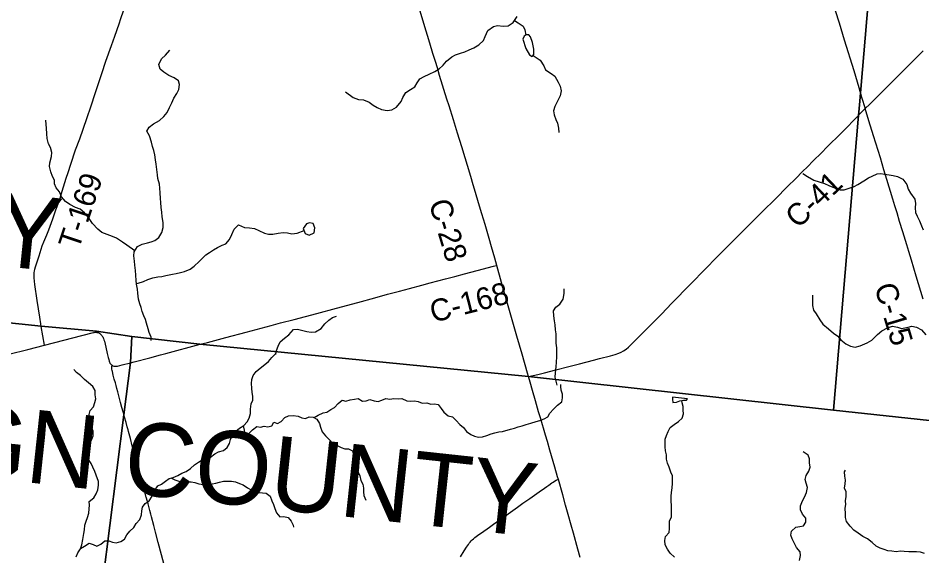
# Model space of a CAD drawing. Extents: x 0 to 1101, y 0 to 440.
# Drawn here: x 372 to 442.1, y 244.3 to 286 of the extents above; entities that cross this region are included whole.
import ezdxf

# ---------------------------------------------------------------- set-up
doc = ezdxf.new("R2010")
doc.units = 0
for name, color, linetype in [('GM_X_County_Road', 7, 'Continuous'), ('GM_X_County_Road_Text', 7, 'Continuous'), ('GM_X_County_Text', 7, 'Continuous'), ('GM_X_Minor_Lake', 7, 'Continuous'), ('GM_X_Minor_River', 7, 'Continuous'), ('GM_X_State_Route', 7, 'Continuous'), ('GM_X_Township', 7, 'Continuous'), ('GM_X_Township_Road', 7, 'Continuous'), ('GM_X_Township_Road_Text', 7, 'Continuous'), ('SH_Cut_Line', 7, 'Continuous')]:
    doc.layers.add(name, color=color, linetype=linetype)

msp = doc.modelspace()

# ---------------------------------------------------------------- linework, layer by layer
at = {"layer": 'GM_X_County_Road'}
msp.add_lwpolyline([(539, 244.322), (539, 402.783), (536.69, 402.914), (536.426, 402.929), (536.173, 402.942), (535.046, 402.998), (535.011, 403), (510.324, 404.394), (509.979, 404.414), (498.864, 405.041), (457.454, 407.541), (450.104, 407.972), (448.107, 408.104), (447.185, 397.096), (444.709, 367.542), (441.919, 334.219), (439.492, 305.784), (437.233, 279.3), (437.137, 278.176), (435.213, 255.629), (445.064, 254.562), (483.107, 250.705), (508.328, 247.799), (515.616, 246.993)], close=True, dxfattribs=at)
for points in [[(258.549, 348.4), (256.033, 323.55), (255.755, 319.941), (254.279, 304.355), (253.117, 292.401), (251.924, 280.12), (251.38, 274.519), (281.529, 271.532), (305.637, 269.297), (307.931, 269.05), (324.455, 267.133), (346.049, 265.027), (373.771, 262.138), (378.061, 261.761), (380.797, 261.323), (386.092, 260.749), (411.56, 258.243), (435.213, 255.629), (437.137, 278.176), (437.233, 279.3), (439.492, 305.784), (441.919, 334.219), (444.709, 367.542)], [(409.108, 266.85), (408.95, 267.398), (408.692, 268.293), (408.505, 268.937), (408.196, 270.012), (407.96, 270.836), (407.7, 271.693), (407.454, 272.513), (407.288, 273.085), (407.09, 273.745), (406.39, 276.043), (406.074, 277.095), (405.757, 278.129), (405.415, 279.214), (405.248, 279.747), (404.679, 281.579), (404.5, 282.168), (404.356, 282.649), (404.16, 283.29), (403.917, 284.072), (403.456, 285.606), (403.171, 286.551)], [(436.917, 278.231), (436.936, 278.251), (437.421, 278.747), (437.677, 279.002)], [(442.167, 264.219), (441.627, 266.023), (441.264, 267.256), (441.057, 267.934), (440.896, 268.449), (440.594, 269.448), (440.348, 270.25), (440.144, 270.928), (439.982, 271.463), (439.823, 271.98), (439.358, 273.513), (439.133, 274.263), (438.852, 275.191), (438.331, 276.883), (437.97, 278.058), (437.677, 279.002)], [(411.567, 258.227), (412.302, 258.395), (412.808, 258.518), (413.692, 258.75), (414.684, 259.008), (415.533, 259.224), (416.615, 259.502), (417.067, 259.616), (417.916, 259.83), (418.29, 259.94), (418.569, 260.041), (418.754, 260.122), (418.931, 260.221), (419.129, 260.356), (419.329, 260.519), (419.613, 260.786), (420.65, 261.831), (421.868, 263.064), (422.683, 263.909), (423.198, 264.448), (423.612, 264.879), (424.204, 265.473), (426.234, 267.529), (427.387, 268.696), (427.927, 269.237), (428.61, 269.924), (429.678, 270.992), (430.736, 272.043), (431.635, 272.937), (432.32, 273.621), (432.795, 274.095), (433.232, 274.528), (433.628, 274.921), (434.31, 275.609), (434.706, 276.004), (435.811, 277.114), (436.273, 277.574), (436.781, 278.093), (436.917, 278.231)], [(386.099, 260.733), (386.673, 260.878), (387.25, 261.028), (388.096, 261.254), (389.681, 261.676), (390.455, 261.882), (391.623, 262.2), (392.344, 262.388), (393.403, 262.654), (395.157, 263.116), (396.683, 263.536), (398.327, 263.981), (399.653, 264.344), (400.642, 264.605), (401.568, 264.85), (402.335, 265.054), (403.306, 265.32), (403.936, 265.487), (405.144, 265.808), (405.847, 265.992), (406.604, 266.193), (407.578, 266.445), (408.863, 266.785), (408.945, 266.807), (409.108, 266.85)], [(411.567, 258.227), (411.485, 258.493), (411.064, 259.956), (410.664, 261.357), (409.941, 263.883), (409.616, 265.05), (409.193, 266.557), (409.108, 266.85)], [(374.049, 260.664), (377.733, 261.619), (377.824, 261.641), (377.894, 261.657), (377.968, 261.66), (378.025, 261.66), (378.086, 261.654), (378.147, 261.646), (378.192, 261.633), (378.241, 261.615), (378.278, 261.593), (378.324, 261.567), (378.375, 261.525), (378.428, 261.476), (378.476, 261.423), (378.514, 261.368), (378.558, 261.303), (378.591, 261.236), (378.619, 261.172), (378.649, 261.087), (378.688, 260.961), (378.793, 260.5), (378.899, 260.027), (378.974, 259.712), (379.017, 259.548), (379.043, 259.421), (379.066, 259.357), (379.092, 259.303), (379.115, 259.263), (379.17, 259.194), (379.225, 259.14), (379.276, 259.101)], [(380.703, 259.3), (380.994, 259.377), (382.218, 259.691), (383.028, 259.905), (383.441, 260.016), (386.099, 260.733)], [(348.992, 254.096), (350.05, 254.366), (351.365, 254.717), (352.592, 255.034), (353.512, 255.274), (354.755, 255.597), (355.295, 255.734), (357.96, 256.413), (360.999, 257.229), (362.306, 257.594), (363.84, 258.009), (365.403, 258.438), (366.73, 258.783), (369.053, 259.375), (371.278, 259.954), (372.737, 260.332), (374.049, 260.664)], [(379.276, 259.101), (379.306, 259.082), (379.346, 259.061), (379.403, 259.041), (379.454, 259.032), (379.505, 259.027), (379.563, 259.026), (379.629, 259.032), (379.7, 259.041), (380.057, 259.13), (380.703, 259.3)], [(413.882, 250.257), (413.829, 250.453), (413.617, 251.206), (413.357, 252.081), (413.232, 252.509), (413.033, 253.187), (412.887, 253.688), (412.493, 255.029), (412.355, 255.493), (412.104, 256.352), (411.874, 257.158), (411.686, 257.803), (411.567, 258.227)], [(415.582, 244.21), (415.4, 244.855), (415.052, 246.073), (414.875, 246.701), (414.645, 247.527), (414.44, 248.263), (414.221, 249.049), (413.882, 250.257)]]:
    msp.add_lwpolyline(points, dxfattribs=at)
at = {"layer": 'GM_X_Minor_Lake'}
msp.add_line((423.902, 256.506), (422.728, 256.636), dxfattribs=at)
for points in [[(411.71, 284.568), (411.587, 284.719), (411.393, 284.723), (411.22, 284.623), (411.136, 284.384), (411.362, 283.66), (411.649, 283.175), (411.863, 283.034), (411.992, 283.203), (411.988, 283.603), (411.885, 284.142)], [(411.885, 284.142), (411.71, 284.568)], [(394.251, 269.329), (394.568, 269.186), (394.948, 269.362), (394.99, 269.75), (394.871, 270.095), (394.598, 270.157), (394.345, 270.07), (394.099, 269.72)], [(394.099, 269.72), (394.251, 269.329)], [(422.728, 256.636), (422.732, 256.479), (422.763, 256.205), (423.048, 256.247), (423.3, 256.346), (423.574, 256.4), (423.813, 256.408), (423.902, 256.506)]]:
    msp.add_lwpolyline(points, dxfattribs=at)
at = {"layer": 'GM_X_Minor_River'}
for points in [[(397.383, 280.315), (397.968, 279.87), (398.376, 279.714), (398.775, 279.684), (399.206, 279.516), (399.521, 279.27), (399.826, 279.104), (400.165, 278.938), (400.62, 278.861), (400.964, 278.912), (401.344, 279.122), (401.695, 279.562), (401.815, 279.88), (402.062, 280.252), (402.42, 280.486), (402.744, 280.697), (402.933, 281.014), (403.144, 281.307), (403.49, 281.495), (403.87, 281.671), (404.296, 281.88), (404.62, 282.069), (404.945, 282.383), (405.214, 282.687), (405.619, 283.022), (405.919, 283.188), (406.287, 283.307), (406.631, 283.404), (406.977, 283.558), (407.334, 283.723), (407.726, 283.955), (408.075, 284.292), (408.195, 284.61), (408.409, 285.063), (408.86, 285.364), (409.158, 285.438), (409.603, 285.407), (409.991, 285.412), (410.373, 285.679), (410.69, 286.142)], [(410.484, 285.84), (410.761, 285.66), (411.155, 285.402), (411.287, 285.113), (411.357, 284.702)], [(382.304, 261.02), (382.306, 261.271), (382.142, 261.64), (382.067, 261.927), (381.95, 262.364), (381.865, 262.662), (381.745, 262.95), (381.614, 263.261), (381.528, 263.572), (381.419, 263.859), (381.335, 264.238), (381.264, 264.697), (381.236, 264.995), (381.175, 265.384), (381.146, 265.671), (381.119, 266.083), (381.081, 266.449), (381.043, 266.862), (381.004, 267.182), (380.966, 267.595), (380.983, 267.903), (381.254, 268.321), (381.611, 268.486), (382.024, 268.604), (382.311, 268.679), (382.598, 268.788), (382.899, 269), (383.146, 269.407), (383.245, 269.782), (383.229, 270.171), (383.169, 270.607), (383.131, 270.973), (383.081, 271.34), (383.054, 271.729), (383.025, 272.027), (382.999, 272.473), (382.972, 272.828), (382.944, 273.16), (382.838, 273.585), (382.809, 273.872), (382.76, 274.273), (382.688, 274.697), (382.638, 275.041), (382.588, 275.419), (382.514, 275.763), (382.418, 276.074), (382.344, 276.395), (382.171, 276.89), (381.984, 277.259), (382.161, 277.576), (382.485, 277.822), (382.958, 278.076), (383.295, 278.39), (383.541, 278.706), (383.742, 279.091), (383.909, 279.454), (384.064, 279.805), (384.288, 280.167), (384.465, 280.495), (384.518, 280.883), (384.421, 281.17), (384.094, 281.394), (383.675, 281.561), (383.292, 281.831), (383, 282.054), (382.904, 282.433), (383.118, 282.875), (383.409, 283.144), (383.758, 283.526)], [(411.932, 283.123), (412.463, 282.76), (412.752, 282.32), (412.883, 282.02), (413.323, 281.738), (413.615, 281.515), (413.88, 281.053), (414.012, 280.753), (414.096, 280.386), (414.031, 279.998), (413.759, 279.489), (413.616, 279.171), (413.507, 278.842), (413.57, 278.532), (413.7, 278.164), (413.808, 277.865), (413.903, 277.485), (413.909, 277.154)], [(381.032, 267.978), (380.422, 268.428), (380.084, 268.64), (379.622, 268.957), (379.316, 269.088), (378.885, 269.233), (378.489, 269.412), (378.163, 269.67), (377.772, 270.1), (377.438, 270.552), (377.137, 270.934), (376.8, 271.215), (376.449, 271.347), (376.008, 271.572), (375.658, 271.796), (375.346, 272.168), (375.193, 272.548), (374.936, 272.85), (374.805, 273.161), (374.8, 273.458), (374.645, 273.747), (374.538, 274.103), (374.432, 274.505), (374.46, 274.802), (374.584, 275.303), (374.612, 275.599), (374.505, 275.978), (374.351, 276.267), (374.256, 276.692), (374.229, 277.047), (374.203, 277.482), (374.174, 277.768), (374.135, 278.112)], [(432.853, 273.971), (433.191, 273.736), (433.688, 273.464), (434.108, 273.33), (434.516, 273.186), (434.845, 273.054), (435.286, 272.852), (435.74, 272.695), (436.037, 272.712), (436.427, 272.842), (436.818, 272.961), (437.117, 273.115), (437.568, 273.404), (437.926, 273.638), (438.214, 273.77), (438.594, 273.945), (438.88, 273.963), (439.176, 273.923), (439.529, 273.86), (439.847, 273.82), (440.189, 273.745), (440.584, 273.532), (440.896, 273.114), (441.015, 272.769), (441.18, 272.458), (441.536, 271.982), (441.586, 271.638), (441.546, 271.319), (441.573, 270.953), (441.693, 270.665), (441.881, 270.307), (442.033, 269.904), (442.164, 269.604)], [(381.167, 265.456), (381.313, 265.462), (381.704, 265.603), (382.049, 265.746), (382.44, 265.887), (382.818, 265.96), (383.138, 266), (383.448, 266.063), (383.952, 266.157), (384.25, 266.231), (384.582, 266.294), (384.892, 266.368), (385.329, 266.566), (385.642, 266.8), (386.037, 267.159), (386.537, 267.664), (386.826, 267.853), (387.138, 268.053), (387.45, 268.242), (387.807, 268.407), (388.106, 268.527), (388.375, 268.865), (388.565, 269.25), (388.744, 269.659), (389.082, 269.995), (389.534, 269.793), (389.945, 269.762), (390.32, 269.71), (390.649, 269.555), (391.101, 269.352), (391.397, 269.278), (391.739, 269.272), (392.163, 269.344), (392.552, 269.394), (392.871, 269.366), (393.224, 269.302), (393.624, 269.352), (394.167, 269.544)], [(413.786, 257.555), (413.723, 257.882), (413.637, 258.169), (413.667, 258.512), (413.71, 258.98), (413.74, 259.356), (413.77, 259.767), (413.777, 260.11), (413.772, 260.453), (413.722, 260.809), (413.718, 261.186), (413.724, 261.529), (413.673, 261.861), (413.635, 262.228), (413.584, 262.56), (413.534, 262.927), (413.507, 263.328), (413.684, 263.622), (413.985, 263.845), (414.255, 264.24), (414.332, 264.662), (414.327, 265.027)], [(433.586, 264.548), (433.59, 264.125), (433.594, 263.748), (433.655, 263.381), (433.866, 263.08), (434.155, 262.629), (434.4, 262.304), (434.838, 261.93), (435.231, 261.603), (435.546, 261.357), (435.78, 261.067), (436.185, 260.762), (436.536, 260.596), (436.899, 260.52), (437.289, 260.616), (437.83, 260.846), (438.188, 261.057), (438.642, 261.494), (438.978, 261.763), (439.405, 262.006), (439.784, 262.125), (440.193, 262.049), (440.488, 261.952), (441.004, 262.057), (441.291, 262.143), (441.643, 262.068), (442.039, 261.844), (442.385, 261.471)], [(391.964, 259.927), (392.023, 260.247), (392.166, 260.575), (392.321, 260.916), (392.647, 261.207), (392.971, 261.464), (393.344, 261.88), (393.664, 261.908), (394.062, 261.798), (394.369, 261.724), (394.71, 261.672), (395.053, 261.7), (395.48, 261.967), (395.772, 262.316), (396.075, 262.607), (396.364, 262.808), (396.674, 262.905)], [(376.836, 244.907), (377.149, 245.084), (377.493, 245.298), (377.801, 245.215), (378.085, 245.076), (378.395, 245.244), (378.717, 245.493), (379.014, 245.502), (379.299, 245.385), (379.606, 245.336), (379.95, 245.447), (380.237, 245.628), (380.411, 245.946), (380.654, 246.241), (380.953, 246.524), (381.15, 246.843), (381.439, 247.149), (381.568, 247.502), (381.593, 247.811), (381.63, 248.097), (381.85, 248.392), (382.148, 248.584), (382.38, 248.947), (382.543, 249.335), (382.833, 249.767), (383.119, 249.89), (383.418, 250.116), (383.706, 250.33), (384.003, 250.408), (384.37, 250.553), (384.692, 250.744), (385.035, 250.856), (385.346, 251.093), (385.668, 251.376), (385.979, 251.602), (386.266, 251.782), (386.587, 251.882), (386.919, 251.982), (387.252, 252.242), (387.539, 252.399), (387.906, 252.499), (388.193, 252.736), (388.379, 253.032), (388.461, 253.34), (388.59, 253.625), (388.855, 253.965), (389.155, 254.226), (389.488, 254.429), (389.753, 254.723), (389.904, 255.008), (389.999, 255.373), (390.001, 255.693), (390.074, 256.116), (390.19, 256.401), (390.182, 256.71), (390.15, 256.996), (390.107, 257.339), (390.076, 257.694), (390.102, 257.991), (390.207, 258.311), (390.45, 258.629), (390.772, 258.877), (391.117, 259.16), (391.416, 259.397), (391.659, 259.704), (391.947, 259.999), (392.005, 260.101)], [(376.501, 244.244), (376.63, 244.563), (376.827, 244.881), (376.944, 245.189), (377.004, 245.589), (377.089, 246.057), (377.137, 246.342), (377.163, 246.697), (377.268, 247.016), (377.362, 247.301), (377.468, 247.632), (377.505, 247.963), (377.531, 248.26), (377.51, 248.546), (377.856, 248.829), (378.052, 249.125), (378.17, 249.444), (378.218, 249.798), (378.221, 250.084), (378.054, 250.589), (377.931, 250.876), (377.785, 251.197), (377.651, 251.484), (377.459, 251.795), (377.325, 252.082), (377.225, 252.369), (377.193, 252.655), (377.367, 252.962), (377.655, 253.246), (377.807, 253.633), (377.822, 253.988), (377.688, 254.332), (377.599, 254.642), (377.499, 254.997), (377.513, 255.294), (377.584, 255.591), (377.827, 255.886), (377.944, 256.205), (378.015, 256.502), (377.972, 256.8), (377.975, 257.154), (377.784, 257.465), (377.444, 257.754), (377.149, 257.997), (376.821, 258.32), (376.526, 258.54), (376.299, 258.783)], [(394.941, 255.041), (395.252, 255.244), (395.642, 255.412), (395.928, 255.478), (396.238, 255.681), (396.525, 255.839), (396.813, 256.145), (397.124, 256.394), (397.409, 256.322), (397.741, 256.411), (398.073, 256.476), (398.359, 256.531), (398.688, 256.322), (398.985, 256.353), (399.272, 256.442), (399.613, 256.336), (399.899, 256.288), (400.196, 256.399), (400.506, 256.534), (400.814, 256.474), (401.134, 256.528), (401.465, 256.49), (401.751, 256.534), (402.126, 256.336), (402.435, 256.333), (402.72, 256.341), (403.017, 256.282), (403.313, 256.176), (403.679, 256.195), (403.986, 256.09), (404.283, 256.11), (404.568, 256.061), (404.794, 255.762), (405.008, 255.462), (405.337, 255.185), (405.679, 255.102), (405.951, 254.813), (406.245, 254.502), (406.54, 254.282), (406.754, 253.959), (407.095, 253.727), (407.391, 253.61), (407.698, 253.539), (407.996, 253.559), (408.339, 253.647), (408.671, 253.781), (408.958, 253.859), (409.255, 253.947), (409.564, 253.979), (410.182, 254.156), (410.48, 254.222), (410.767, 254.334), (411.087, 254.399), (411.385, 254.5), (411.752, 254.622), (412.152, 254.756), (412.45, 254.81), (412.782, 254.956), (413.069, 255.102), (413.22, 255.398), (413.509, 255.704), (413.809, 256.021), (414.142, 256.281), (414.213, 256.578), (414.193, 256.864), (414.104, 257.162), (414.084, 257.448), (414.085, 257.609)], [(422.887, 244.213), (422.547, 244.537), (422.356, 244.836), (422.165, 245.181), (422.145, 245.524), (422.193, 245.832), (422.482, 246.127), (422.507, 246.436), (422.498, 246.744), (422.501, 247.042), (422.652, 247.338), (422.655, 247.635), (422.66, 248.253), (422.629, 248.539), (422.621, 248.951), (422.669, 249.248), (422.706, 249.591), (422.732, 249.945), (422.735, 250.231), (422.726, 250.528), (422.615, 250.827), (422.469, 251.194), (422.335, 251.516), (422.269, 251.825), (422.272, 252.168), (422.184, 252.478), (422.164, 252.787), (422.169, 253.37), (422.263, 253.667), (422.391, 253.963), (422.554, 254.27), (422.864, 254.507), (423.198, 254.733), (423.485, 254.994), (423.591, 255.336), (423.56, 255.622), (423.551, 255.908), (423.485, 256.195), (423.464, 256.378)], [(389.435, 254.396), (389.507, 254.062), (389.561, 253.742), (389.871, 253.819), (390.159, 254.091), (390.504, 254.35), (390.789, 254.314), (391.075, 254.391), (391.36, 254.331), (391.658, 254.397), (391.809, 254.693), (392.093, 254.599), (392.392, 254.733), (392.669, 255.062), (392.967, 255.174), (393.321, 255.216), (393.698, 255.167), (393.982, 255.039), (394.267, 254.979), (394.554, 255.102), (394.862, 255.088), (395.157, 254.913), (395.349, 254.58), (395.437, 254.293), (395.571, 253.937), (395.82, 253.626), (396.114, 253.338), (396.442, 252.991), (396.727, 252.886), (397.034, 252.734), (397.33, 252.629), (397.616, 252.614), (397.911, 252.463), (397.989, 252.176), (397.963, 251.868), (398.006, 251.524), (398.14, 251.18), (398.343, 250.869), (398.5, 250.536), (398.565, 250.181), (398.711, 249.882), (398.777, 249.573), (398.774, 249.287), (398.806, 249), (398.951, 248.633)], [(432.582, 243.963), (432.654, 244.363), (432.646, 244.649), (432.352, 244.972), (432.183, 245.271), (432.015, 245.638), (431.903, 245.937), (431.974, 246.233), (432.285, 246.539), (432.606, 246.605), (432.892, 246.648), (433.066, 246.932), (433.069, 247.253), (432.82, 247.552), (432.663, 247.885), (432.654, 248.206), (432.806, 248.582), (432.957, 248.878), (433.132, 249.242), (433.192, 249.619), (433.104, 249.952), (433.027, 250.25), (433.087, 250.569), (433.318, 250.888), (433.401, 251.196), (433.358, 251.539), (433.361, 251.837), (433.26, 252.123), (432.931, 252.344), (432.863, 252.39)], [(442.262, 244.514), (441.954, 244.62), (441.646, 244.645), (441.361, 244.648), (441.052, 244.639), (440.699, 244.665), (440.402, 244.68), (440.07, 244.648), (439.751, 244.686), (439.443, 244.723), (439.146, 244.817), (438.827, 244.912), (438.521, 245.086), (438.215, 245.352), (437.863, 245.641), (437.499, 245.827), (437.125, 246.094), (436.807, 246.326), (436.512, 246.626), (436.23, 246.983), (436.141, 247.293), (436.144, 247.59), (436.125, 248.025), (436.162, 248.31), (436.153, 248.597), (436.202, 248.916), (436.193, 249.282), (436.059, 249.581), (436.13, 249.901), (436.156, 250.186), (436.102, 250.507), (436.082, 250.839), (436.14, 250.964)], [(383.83, 250.363), (384.139, 250.223), (384.458, 250.129), (384.743, 250.081), (385.097, 250.066), (385.405, 250.074), (385.69, 250.015), (385.998, 249.92), (386.34, 249.871), (386.717, 249.879), (387.037, 249.911), (387.323, 249.965), (387.61, 250.042), (387.93, 250.108), (388.227, 250.128), (388.535, 250.114), (388.844, 250.077), (389.162, 249.948), (389.447, 249.842), (389.776, 249.588), (390.072, 249.436), (390.356, 249.331), (390.641, 249.237), (390.949, 249.222), (391.234, 249.185), (391.529, 248.954), (391.663, 248.598), (391.786, 248.311), (391.909, 247.99), (392.02, 247.668), (392.292, 247.357), (392.6, 247.377), (392.92, 247.305), (393.168, 247.017), (393.314, 246.707), (393.347, 246.558)]]:
    msp.add_lwpolyline(points, dxfattribs=at)
at = {"layer": 'GM_X_State_Route'}
for points in [[(435.072, 287.513), (435.645, 285.66), (436.041, 284.341), (436.782, 281.954), (437.175, 280.646)], [(437.175, 280.646), (437.399, 279.901), (437.677, 279.002), (438.036, 279.347), (439.548, 280.866), (441.444, 282.766), (442.162, 283.484)]]:
    msp.add_lwpolyline(points, dxfattribs=at)
at = {"layer": 'GM_X_Township'}
for points in [[(189.224, 280.089), (205.419, 278.858), (219.953, 277.58), (235.998, 275.889), (239.628, 275.54), (251.141, 274.543), (251.38, 274.519), (281.529, 271.532), (305.637, 269.297), (307.931, 269.05), (324.455, 267.133), (346.049, 265.027), (373.771, 262.138), (378.061, 261.761), (380.797, 261.323), (380.697, 259.316), (380.197, 255.256), (378.028, 238.099), (373.82, 204.757), (373.469, 201.961), (371.877, 189.376), (367.226, 152.429)], [(456.87, 41.812), (429.195, 44.697), (407.625, 46.582), (393.244, 47.835), (358.093, 49.313), (354.24, 49.634), (354.518, 51.702), (355.546, 60.287), (359.256, 91.672), (367.226, 152.429), (371.877, 189.376), (373.469, 201.961), (373.82, 204.757), (378.028, 238.099), (380.197, 255.256), (380.697, 259.316), (380.797, 261.323), (386.092, 260.749), (411.56, 258.243), (435.213, 255.629), (445.064, 254.562)]]:
    msp.add_lwpolyline(points, dxfattribs=at)
at = {"layer": 'GM_X_Township_Road'}
msp.add_line((374.049, 260.664), (373.778, 262.122), dxfattribs=at)
for points in [[(373.778, 262.122), (373.75, 262.323), (373.67, 262.844), (373.475, 264.12), (373.294, 265.357), (373.257, 265.629), (373.242, 265.882), (373.232, 266.044), (373.232, 266.17), (373.246, 266.309), (373.257, 266.397), (373.291, 266.567), (373.336, 266.732), (373.615, 267.599), (373.869, 268.358), (373.991, 268.67), (374.227, 269.217), (374.379, 269.616), (374.59, 270.187), (374.687, 270.471), (374.919, 271.156), (375.188, 271.885), (375.408, 272.595), (375.718, 273.614), (375.86, 274.057), (376.077, 274.694), (376.454, 275.797), (376.773, 276.658), (377.319, 278.244), (377.647, 279.231), (377.968, 280.188), (378.483, 281.724), (378.806, 282.675), (379.233, 283.888), (379.488, 284.611), (379.816, 285.586), (379.953, 285.987), (380.155, 286.595)], [(380.204, 255.24), (380.13, 255.503), (380.039, 255.842), (379.934, 256.211), (379.848, 256.524), (379.717, 257.034), (379.652, 257.301), (379.59, 257.535), (379.536, 257.732), (379.448, 258.037), (379.37, 258.325), (379.299, 258.609), (379.282, 258.699), (379.268, 258.813), (379.263, 258.893), (379.265, 258.976), (379.276, 259.101)], [(380.52, 254.087), (380.452, 254.328), (380.361, 254.667), (380.252, 255.067), (380.204, 255.24)], [(382.065, 248.357), (382.02, 248.53), (381.925, 248.886), (381.715, 249.678), (381.49, 250.482), (381.381, 250.874), (381.261, 251.323), (381.075, 252.026), (380.906, 252.636), (380.842, 252.869), (380.696, 253.434), (380.553, 253.966), (380.52, 254.087)], [(406.288, 244.261), (406.575, 244.721), (406.761, 245), (406.905, 245.206), (406.975, 245.304), (407.051, 245.398), (407.134, 245.491), (407.203, 245.561), (407.305, 245.655), (407.406, 245.744), (407.501, 245.82), (407.609, 245.903), (407.791, 246.035), (407.911, 246.122), (408.541, 246.558), (408.862, 246.781), (409.71, 247.389), (410.181, 247.724), (410.712, 248.104), (411.119, 248.399), (411.669, 248.784), (412.023, 249.024), (412.406, 249.291), (412.802, 249.569), (412.985, 249.698), (413.152, 249.816), (413.382, 249.975), (413.49, 250.048), (413.589, 250.111), (413.707, 250.182), (413.767, 250.215), (413.83, 250.242), (413.882, 250.257)], [(383.295, 243.723), (382.864, 245.364), (382.652, 246.156), (382.513, 246.678), (382.336, 247.343), (382.279, 247.556), (382.199, 247.835), (382.065, 248.357)]]:
    msp.add_lwpolyline(points, dxfattribs=at)
at = {"layer": 'SH_Cut_Line'}
for points in [[(445.064, 254.562), (435.213, 255.629), (411.56, 258.243), (386.092, 260.749), (380.797, 261.323), (378.061, 261.761), (373.771, 262.138), (346.049, 265.027), (324.455, 267.133), (307.931, 269.05), (305.637, 269.297), (281.529, 271.532), (251.38, 274.519), (251.141, 274.543), (239.628, 275.54), (235.998, 275.889), (219.953, 277.58), (205.419, 278.858), (189.224, 280.089)], [(189.224, 280.089), (205.419, 278.858), (219.953, 277.58), (235.998, 275.889), (239.628, 275.54), (251.141, 274.543), (251.38, 274.519), (281.529, 271.532), (305.637, 269.297), (307.931, 269.05), (324.455, 267.133), (346.049, 265.027), (373.771, 262.138), (378.061, 261.761), (380.797, 261.323), (386.092, 260.749), (411.56, 258.243), (435.213, 255.629), (445.064, 254.562)]]:
    msp.add_lwpolyline(points, dxfattribs=at)

# ---------------------------------------------------------------- texts
at = {"layer": 'GM_X_County_Road_Text'}
for s, rotation, p in [('C-41', 43.54396, (432.471, 269.639)), ('C-28', 286.69938, (403.819, 271.71)), ('C-168', 14.43575, (404.169, 262.393)), ('C-15', 286.69938, (438.369, 265.21))]:
    msp.add_text(s, height=1.7045, rotation=rotation, dxfattribs=at).set_placement(p)
at = {"layer": 'GM_X_County_Text'}
for s, rotation, p in [('LOGAN COUNTY', 354.10872, (314.55, 272.594)), ('CHAMPAIGN COUNTY', 353.83976, (332.148, 254.403))]:
    msp.add_text(s, height=5.68182, rotation=rotation, dxfattribs=at).set_placement(p)
at = {"layer": 'GM_X_Township_Road_Text'}
msp.add_text('T-169', height=1.7045, rotation=71.47586, dxfattribs=at).set_placement((376.686, 267.996))

doc.saveas('drawing.dxf')
